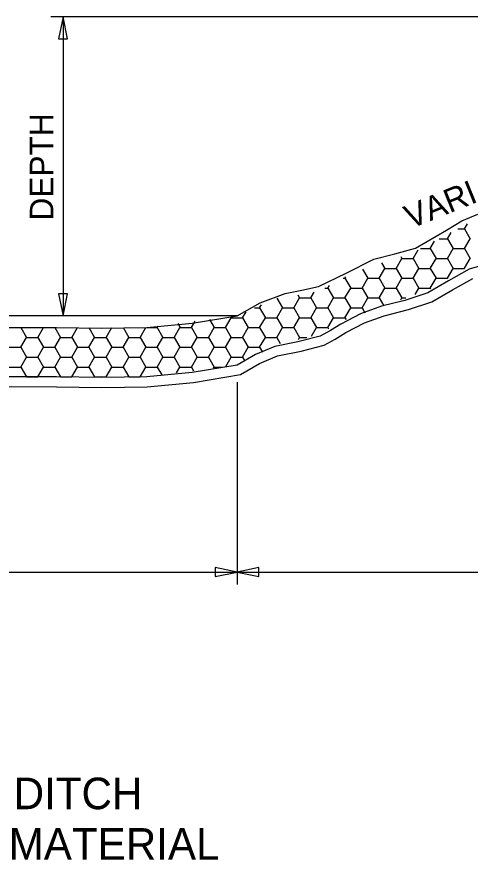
# Model space of a CAD drawing. Extents: x -439.1 to -407.9, y -458.1 to -436.2.
# Drawn here: x -427.62 to -424.75, y -446.22 to -440.88 of the extents above; entities that cross this region are included whole.
import ezdxf

# ---------------------------------------------------------------- set-up
doc = ezdxf.new("R2010")
doc.units = 0
doc.layers.add('Default', color=7, linetype='Continuous')

msp = doc.modelspace()

# ---------------------------------------------------------------- linework, layer by layer
at = {"layer": 'Default'}
for p, q in [((-421.6463, -440.8769), (-427.4066, -440.8769)), ((-427.3285, -440.8769), (-427.3285, -442.7708)), ((-424.7826, -442.2208), (-424.7642, -442.1888)), ((-424.8909, -442.2833), (-424.868, -442.2436)), ((-424.8247, -442.2208), (-424.7826, -442.2208)), ((-424.7826, -442.2208), (-424.7466, -442.2833)), ((-424.9991, -442.3458), (-424.9718, -442.2984)), ((-424.9431, -442.2833), (-424.8909, -442.2833)), ((-424.8909, -442.2833), (-424.8548, -442.3458)), ((-424.7826, -442.3458), (-424.7466, -442.2833)), ((-425.1074, -442.4083), (-425.0756, -442.3532)), ((-425.0615, -442.3458), (-424.9991, -442.3458)), ((-424.9991, -442.3458), (-424.9631, -442.4083)), ((-424.8909, -442.4083), (-424.8548, -442.3458)), ((-424.8548, -442.3458), (-424.7826, -442.3458)), ((-424.7826, -442.3458), (-424.7466, -442.4083)), ((-425.2156, -442.4708), (-425.1796, -442.4083)), ((-425.1871, -442.3953), (-425.1796, -442.4083)), ((-425.1796, -442.4083), (-425.1074, -442.4083)), ((-425.1074, -442.4083), (-425.0713, -442.4708)), ((-424.9991, -442.4708), (-424.9631, -442.4083)), ((-424.9631, -442.4083), (-424.8909, -442.4083)), ((-424.8909, -442.4083), (-424.8548, -442.4708)), ((-424.7823, -442.4701), (-424.7466, -442.4083)), ((-425.4298, -442.4748), (-425.3961, -442.5333)), ((-425.3239, -442.5333), (-425.2878, -442.4708)), ((-425.3084, -442.435), (-425.2878, -442.4708)), ((-425.2878, -442.4708), (-425.2156, -442.4708)), ((-425.2156, -442.4708), (-425.1796, -442.5333)), ((-425.1074, -442.5333), (-425.0713, -442.4708)), ((-425.0713, -442.4708), (-424.9991, -442.4708)), ((-424.9991, -442.4708), (-424.9631, -442.5333)), ((-424.8909, -442.5333), (-424.8548, -442.4708)), ((-424.8548, -442.4708), (-424.7833, -442.4708)), ((-425.5404, -442.5333), (-425.5348, -442.5236)), ((-425.6487, -442.5958), (-425.6396, -442.5801)), ((-425.5528, -442.5333), (-425.5404, -442.5333)), ((-425.5404, -442.5333), (-425.5043, -442.5958)), ((-425.4321, -442.5958), (-425.3961, -442.5333)), ((-425.3961, -442.5333), (-425.3239, -442.5333)), ((-425.3239, -442.5333), (-425.2878, -442.5958)), ((-425.2156, -442.5958), (-425.1796, -442.5333)), ((-425.1796, -442.5333), (-425.1074, -442.5333)), ((-425.1074, -442.5333), (-425.0713, -442.5958)), ((-424.9991, -442.5958), (-424.9631, -442.5333)), ((-424.9631, -442.5333), (-424.8909, -442.5333)), ((-424.8909, -442.5333), (-424.8895, -442.5357)), ((-425.8404, -442.6387), (-425.8291, -442.6583)), ((-425.7569, -442.6583), (-425.7356, -442.6215)), ((-425.6687, -442.5958), (-425.6487, -442.5958)), ((-425.6487, -442.5958), (-425.6126, -442.6583)), ((-425.5404, -442.6583), (-425.5043, -442.5958)), ((-425.5043, -442.5958), (-425.4321, -442.5958)), ((-425.4321, -442.5958), (-425.3961, -442.6583)), ((-425.3239, -442.6583), (-425.2878, -442.5958)), ((-425.2878, -442.5958), (-425.2156, -442.5958)), ((-425.2156, -442.5958), (-425.1796, -442.6583)), ((-425.0948, -442.6365), (-425.0713, -442.5958)), ((-425.0713, -442.5958), (-424.9991, -442.5958)), ((-424.9991, -442.5958), (-424.9962, -442.6009)), ((-425.9722, -442.6604), (-425.9373, -442.7208)), ((-425.8652, -442.7208), (-425.8291, -442.6583)), ((-425.8291, -442.6583), (-425.7569, -442.6583)), ((-425.7569, -442.6583), (-425.7208, -442.7208)), ((-425.6487, -442.7208), (-425.6126, -442.6583)), ((-425.6126, -442.6583), (-425.5404, -442.6583)), ((-425.5404, -442.6583), (-425.5043, -442.7208)), ((-425.4322, -442.7208), (-425.3961, -442.6583)), ((-425.3961, -442.6583), (-425.3239, -442.6583)), ((-425.3239, -442.6583), (-425.2949, -442.7085)), ((-425.1859, -442.6692), (-425.1796, -442.6583)), ((-425.1796, -442.6583), (-425.1555, -442.6583)), ((-426.1899, -442.7833), (-426.1681, -442.7454)), ((-426.1134, -442.7208), (-426.0817, -442.7208)), ((-426.0817, -442.7208), (-426.0705, -442.7015)), ((-426.0817, -442.7208), (-426.0456, -442.7833)), ((-425.9734, -442.7833), (-425.9373, -442.7208)), ((-425.9373, -442.7208), (-425.8652, -442.7208)), ((-425.8652, -442.7208), (-425.8291, -442.7833)), ((-425.7569, -442.7833), (-425.7208, -442.7208)), ((-425.7208, -442.7208), (-425.6487, -442.7208)), ((-425.6487, -442.7208), (-425.6126, -442.7833)), ((-425.5404, -442.7833), (-425.5043, -442.7208)), ((-425.5043, -442.7208), (-425.4321, -442.7208)), ((-425.4321, -442.7208), (-425.4143, -442.7518)), ((-429.6624, -442.7704), (-426.2249, -442.7704)), ((-426.4003, -442.7938), (-426.3703, -442.8458)), ((-426.2982, -442.8458), (-426.2621, -442.7833)), ((-426.2661, -442.7763), (-426.2621, -442.7833)), ((-426.2621, -442.7833), (-426.2245, -442.7833)), ((-426.2245, -442.7833), (-426.1899, -442.7833)), ((-426.1899, -442.7833), (-426.1538, -442.8458)), ((-426.0817, -442.8458), (-426.0456, -442.7833)), ((-426.0456, -442.7833), (-425.9734, -442.7833)), ((-425.9734, -442.7833), (-425.9373, -442.8458)), ((-425.8652, -442.8458), (-425.8291, -442.7833)), ((-425.8291, -442.7833), (-425.7569, -442.7833)), ((-425.7569, -442.7833), (-425.7208, -442.8458)), ((-425.6487, -442.8458), (-425.6126, -442.7833)), ((-425.6126, -442.7833), (-425.5404, -442.7833)), ((-425.5404, -442.7833), (-425.5336, -442.7951)), ((-427.5972, -442.8458), (-427.5611, -442.9083)), ((-427.489, -442.9083), (-427.4529, -442.8458)), ((-427.3807, -442.8458), (-427.3446, -442.9083)), ((-427.2725, -442.9083), (-427.2364, -442.8458)), ((-427.1642, -442.8458), (-427.1281, -442.9083)), ((-427.0559, -442.9083), (-427.0199, -442.8458)), ((-426.9477, -442.8458), (-426.9116, -442.9083)), ((-426.8394, -442.9083), (-426.8034, -442.8458)), ((-426.7972, -442.8458), (-426.7312, -442.8458)), ((-426.7312, -442.8458), (-426.7258, -442.8364)), ((-426.7312, -442.8458), (-426.6951, -442.9083)), ((-426.6229, -442.9083), (-426.5869, -442.8458)), ((-426.6016, -442.8202), (-426.5868, -442.8458)), ((-426.5869, -442.8458), (-426.5147, -442.8458)), ((-426.5147, -442.8458), (-426.4916, -442.8058)), ((-426.5147, -442.8458), (-426.4786, -442.9083)), ((-426.4064, -442.9083), (-426.3703, -442.8458)), ((-426.3703, -442.8458), (-426.2982, -442.8458)), ((-426.2982, -442.8458), (-426.2621, -442.9083)), ((-426.1899, -442.9083), (-426.1538, -442.8458)), ((-426.1538, -442.8458), (-426.0817, -442.8458)), ((-426.0817, -442.8458), (-426.0456, -442.9083)), ((-425.9734, -442.9083), (-425.9373, -442.8458)), ((-425.9373, -442.8458), (-425.8652, -442.8458)), ((-425.8652, -442.8458), (-425.8291, -442.9083)), ((-425.7528, -442.9011), (-425.7208, -442.8458)), ((-425.7208, -442.8458), (-425.6487, -442.8458)), ((-425.6487, -442.8458), (-425.644, -442.8538)), ((-427.5972, -442.9708), (-427.5611, -442.9083)), ((-427.5611, -442.9083), (-427.489, -442.9083)), ((-427.489, -442.9083), (-427.4529, -442.9708)), ((-427.3807, -442.9708), (-427.3446, -442.9083)), ((-427.3446, -442.9083), (-427.2724, -442.9083)), ((-427.2724, -442.9083), (-427.2364, -442.9708)), ((-427.1642, -442.9708), (-427.1281, -442.9083)), ((-427.1281, -442.9083), (-427.0559, -442.9083)), ((-427.0559, -442.9083), (-427.0199, -442.9708)), ((-426.9477, -442.9708), (-426.9116, -442.9083)), ((-426.9116, -442.9083), (-426.8394, -442.9083)), ((-426.8394, -442.9083), (-426.8034, -442.9708)), ((-426.7312, -442.9708), (-426.6951, -442.9083)), ((-426.6951, -442.9083), (-426.6229, -442.9083)), ((-426.6229, -442.9083), (-426.5869, -442.9708)), ((-426.5147, -442.9708), (-426.4786, -442.9083)), ((-426.4786, -442.9083), (-426.4064, -442.9083)), ((-426.4064, -442.9083), (-426.3703, -442.9708)), ((-426.2982, -442.9708), (-426.2621, -442.9083)), ((-426.2621, -442.9083), (-426.2245, -442.9083)), ((-426.2245, -442.9083), (-426.1899, -442.9083)), ((-426.1899, -442.9083), (-426.1538, -442.9708)), ((-426.0817, -442.9708), (-426.0456, -442.9083)), ((-426.0456, -442.9083), (-425.9734, -442.9083)), ((-425.9734, -442.9083), (-425.9506, -442.9479)), ((-425.8363, -442.9209), (-425.8291, -442.9083)), ((-425.8291, -442.9083), (-425.7832, -442.9083)), ((-427.6694, -442.9708), (-427.5972, -442.9708)), ((-427.5972, -442.9708), (-427.5611, -443.0333)), ((-427.489, -443.0333), (-427.4529, -442.9708)), ((-427.4529, -442.9708), (-427.3807, -442.9708)), ((-427.3807, -442.9708), (-427.3446, -443.0333)), ((-427.2724, -443.0333), (-427.2364, -442.9708)), ((-427.2364, -442.9708), (-427.1642, -442.9708)), ((-427.1642, -442.9708), (-427.1281, -443.0333)), ((-427.0559, -443.0333), (-427.0199, -442.9708)), ((-427.0199, -442.9708), (-426.9477, -442.9708)), ((-426.9477, -442.9708), (-426.9116, -443.0333)), ((-426.8394, -443.0333), (-426.8034, -442.9708)), ((-426.8034, -442.9708), (-426.7312, -442.9708)), ((-426.7312, -442.9708), (-426.6951, -443.0333)), ((-426.6229, -443.0333), (-426.5869, -442.9708)), ((-426.5869, -442.9708), (-426.5147, -442.9708)), ((-426.5147, -442.9708), (-426.4786, -443.0333)), ((-426.4064, -443.0333), (-426.3703, -442.9708)), ((-426.3703, -442.9708), (-426.2982, -442.9708)), ((-426.2982, -442.9708), (-426.2621, -443.0333)), ((-426.1899, -443.0333), (-426.1538, -442.9708)), ((-426.1538, -442.9708), (-426.0817, -442.9708)), ((-426.0817, -442.9708), (-426.0636, -443.0021)), ((-427.5972, -443.0958), (-427.5611, -443.0333)), ((-427.5611, -443.0333), (-427.489, -443.0333)), ((-427.489, -443.0333), (-427.4529, -443.0958)), ((-427.3807, -443.0958), (-427.3446, -443.0333)), ((-427.3446, -443.0333), (-427.2724, -443.0333)), ((-427.2725, -443.0333), (-427.2364, -443.0958)), ((-427.1642, -443.0958), (-427.1281, -443.0333)), ((-427.1281, -443.0333), (-427.0559, -443.0333)), ((-427.0559, -443.0333), (-427.0199, -443.0958)), ((-426.9477, -443.0958), (-426.9116, -443.0333)), ((-426.9116, -443.0333), (-426.8394, -443.0333)), ((-426.8394, -443.0333), (-426.8034, -443.0958)), ((-426.7312, -443.0958), (-426.6951, -443.0333)), ((-426.6951, -443.0333), (-426.6229, -443.0333)), ((-426.6229, -443.0333), (-426.5869, -443.0958)), ((-426.5147, -443.0958), (-426.4786, -443.0333)), ((-426.4786, -443.0333), (-426.4064, -443.0333)), ((-426.4064, -443.0333), (-426.3703, -443.0958)), ((-426.2964, -443.0927), (-426.2621, -443.0333)), ((-426.2621, -443.0333), (-426.2245, -443.0333)), ((-426.2245, -443.0333), (-426.1899, -443.0333)), ((-426.1899, -443.0333), (-426.1754, -443.0585)), ((-427.6694, -443.0958), (-427.5972, -443.0958)), ((-427.5972, -443.0958), (-427.5611, -443.1583)), ((-427.489, -443.1583), (-427.4529, -443.0958)), ((-427.4529, -443.0958), (-427.3807, -443.0958)), ((-427.3807, -443.0958), (-427.3446, -443.1583)), ((-427.2725, -443.1583), (-427.2364, -443.0958)), ((-427.2364, -443.0958), (-427.1642, -443.0958)), ((-427.1642, -443.0958), (-427.1281, -443.1583)), ((-427.0559, -443.1583), (-427.0199, -443.0958)), ((-427.0199, -443.0958), (-426.9477, -443.0958)), ((-426.9477, -443.0958), (-426.9116, -443.1583)), ((-426.8394, -443.1583), (-426.8034, -443.0958)), ((-426.8034, -443.0958), (-426.7312, -443.0958)), ((-426.7312, -443.0958), (-426.7023, -443.1459)), ((-426.6087, -443.1336), (-426.5869, -443.0958)), ((-426.5869, -443.0958), (-426.5147, -443.0958)), ((-426.5147, -443.0958), (-426.501, -443.1195)), ((-426.3745, -443.1029), (-426.3703, -443.0958)), ((-426.3703, -443.0958), (-426.3197, -443.0958)), ((-427.5611, -443.1583), (-427.489, -443.1583)), ((-427.5611, -443.1583), (-427.5611, -443.1583)), ((-427.489, -443.1583), (-427.4889, -443.1583)), ((-427.3446, -443.1583), (-427.2724, -443.1583)), ((-427.3446, -443.1583), (-427.3446, -443.1583)), ((-427.2724, -443.1583), (-427.2724, -443.1583)), ((-427.1281, -443.1583), (-427.0559, -443.1583)), ((-427.1281, -443.1583), (-427.1281, -443.1583)), ((-427.0559, -443.1583), (-427.0559, -443.1583)), ((-426.9116, -443.1583), (-426.8394, -443.1583)), ((-426.9116, -443.1583), (-426.9116, -443.1583)), ((-426.8394, -443.1583), (-426.8394, -443.1583)), ((-426.2245, -443.1927), (-426.2245, -444.4731)), ((-429.662, -444.395), (-426.2245, -444.395)), ((-426.2245, -444.395), (-421.537, -444.395))]:
    msp.add_line(p, q, dxfattribs=at)
for points in [[(-427.2998, -441.0152), (-427.3285, -440.8769), (-427.3572, -441.0152)], [(-427.3572, -442.6325), (-427.3285, -442.7708), (-427.2998, -442.6325)], [(-426.3628, -444.4237), (-426.2245, -444.395), (-426.3628, -444.3663)], [(-426.0862, -444.3663), (-426.2245, -444.395), (-426.0862, -444.4237)]]:
    msp.add_lwpolyline(points, close=True, dxfattribs=at)
for points in [[(-426.2245, -442.7708), (-426.0775, -442.6888), (-425.92, -442.631), (-425.8138, -442.6098), (-425.7092, -442.5855), (-425.5328, -442.5009), (-425.3566, -442.4134), (-425.2246, -442.3793), (-425.0935, -442.3431), (-424.8968, -442.2285), (-424.7999, -442.1687), (-424.6969, -442.1269)], [(-424.6062, -442.4335), (-424.7533, -442.4767), (-424.8847, -442.5499), (-425.015, -442.6255), (-425.16, -442.6734), (-425.3098, -442.7109), (-425.4422, -442.7587), (-425.5674, -442.8238), (-425.6319, -442.8642), (-425.6982, -442.8996), (-425.8393, -442.937), (-425.9847, -442.9657), (-426.1085, -443.0158), (-426.2245, -443.0833)], [(-426.2028, -443.143), (-426.0831, -443.0729), (-425.9676, -443.0258), (-425.8183, -442.9958), (-425.6734, -442.9569), (-425.6032, -442.9197), (-425.5349, -442.8772), (-425.4171, -442.816), (-425.2925, -442.7709), (-425.1382, -442.732), (-424.9889, -442.6822), (-424.8595, -442.6072), (-424.7291, -442.5343)], [(-429.662, -442.7708), (-429.3768, -442.8186), (-429.0891, -442.8458), (-428.8028, -442.8505), (-428.5161, -442.8458), (-428.2296, -442.8449), (-427.9432, -442.8458), (-427.6568, -442.8449), (-427.3703, -442.8458), (-427.0837, -442.8505), (-426.7974, -442.8458), (-426.5097, -442.8186), (-426.2245, -442.7708)], [(-426.2245, -443.0833), (-426.5097, -443.1311), (-426.7974, -443.1583), (-427.0837, -443.163), (-427.3703, -443.1583), (-427.6568, -443.1574), (-427.9432, -443.1583), (-428.2296, -443.1574), (-428.5161, -443.1583), (-428.8028, -443.163), (-429.0891, -443.1583), (-429.3768, -443.1311), (-429.662, -443.0833)], [(-429.6696, -443.1454), (-429.3845, -443.1931), (-429.0923, -443.2207), (-428.804, -443.2255), (-428.5153, -443.2208), (-428.2292, -443.2199), (-427.9432, -443.2208), (-427.6572, -443.2199), (-427.3711, -443.2208), (-427.0825, -443.2255), (-426.7941, -443.2207), (-426.502, -443.1931), (-426.2028, -443.143)]]:
    msp.add_lwpolyline(points, dxfattribs=at)

# ---------------------------------------------------------------- texts
for s, rotation, p in [('DEPTH', 90, (-427.3898, -442.1676)), ('VARIABLE', 22, (-425.1248, -442.2225))]:
    msp.add_text(s, height=0.15, rotation=rotation, dxfattribs=at).set_placement(p)
for s, p in [('FLAT BOTTOM DITCH', (-429.5885, -445.898)), ('WITHOUT BEDDING MATERIAL', (-430.2885, -446.218))]:
    msp.add_text(s, height=0.2, dxfattribs=at).set_placement(p)

doc.saveas('drawing.dxf')
